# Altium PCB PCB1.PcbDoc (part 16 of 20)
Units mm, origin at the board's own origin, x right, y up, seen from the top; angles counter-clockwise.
Board outline 294.51 x 138.18 mm, 12 copper layers (Top Layer 1 _Signal, L2_GND, L3_Signals, L4_GND, L5_POWER, L6_Signals, L7_GND, L8_Signals, L9_GND, L10_POWER, L11_GND, Bottom Layer_Signals), stack 1.788 mm thick; 1254 components, 836 nets, 5699 pads, 2073 vias.
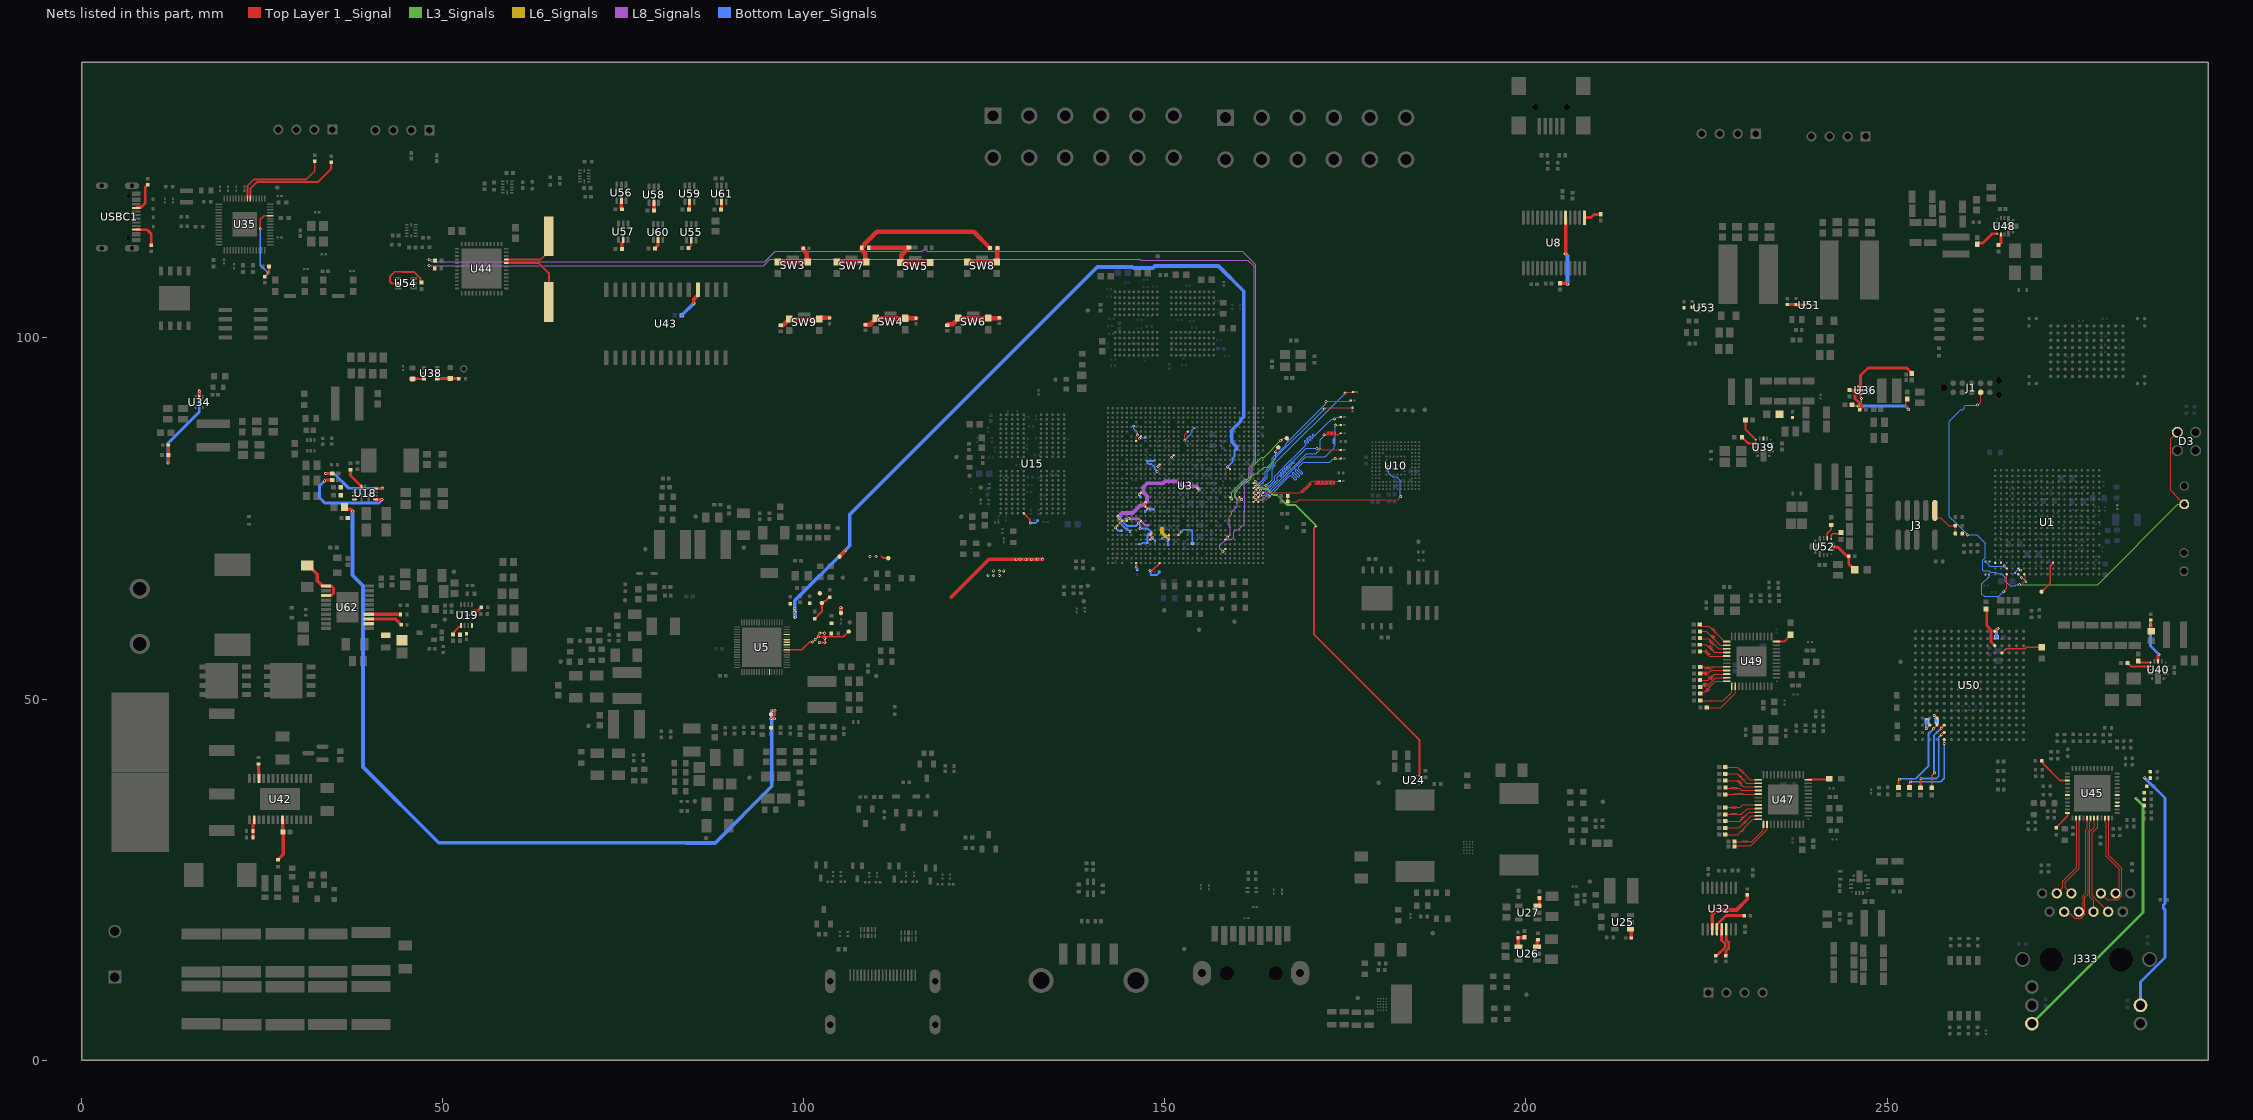
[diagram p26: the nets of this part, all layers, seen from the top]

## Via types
v1: diameter 0.4, hole 0.2, Top Layer 1 _Signal to Bottom Layer_Signals, 2009 vias
v2: diameter 0.508, hole 0.254, Top Layer 1 _Signal to Bottom Layer_Signals, 36 vias
v3: diameter 0.5, hole 0.2, Top Layer 1 _Signal to Bottom Layer_Signals, 12 vias
v4: diameter 1.27, hole 0.711, Top Layer 1 _Signal to Bottom Layer_Signals, 6 vias
v5: diameter 0.3, hole 0.2, Top Layer 1 _Signal to Bottom Layer_Signals, 5 vias
v6: diameter 0.254, hole 0.2, Top Layer 1 _Signal to Bottom Layer_Signals, 3 vias
v7: diameter 0.305, hole 0.2, Top Layer 1 _Signal to Bottom Layer_Signals, 1 vias
v8: diameter 0.254, hole 0.152, Top Layer 1 _Signal to Bottom Layer_Signals, 1 vias

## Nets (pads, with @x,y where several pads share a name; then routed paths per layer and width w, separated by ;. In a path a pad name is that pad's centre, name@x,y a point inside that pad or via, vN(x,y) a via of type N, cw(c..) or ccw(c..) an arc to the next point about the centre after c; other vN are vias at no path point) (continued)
NetR56_2: R56.2 U3.Y33 | length 19.5
  Top Layer 1 _Signal w0.132: U3.Y33@162.929,77.928 162.942,77.928 163.228,78.215 v1(163.241,78.215) ; v1(172.025,86.598) 172.416,86.598 172.482,86.598 172.482,86.996 172.639,86.996 172.639,86.572 172.797,86.572 172.797,86.996 172.954,86.996 172.954,86.572 173.111,86.572 173.111,86.996 173.268,86.996 173.268,86.572 173.425,86.572 173.425,86.996 173.583,86.996 173.583,86.572 173.74,86.572 173.74,86.662 173.897,86.662 173.897,86.598 173.993,86.598 174.06,86.598 174.258,86.796 R56.2@174.374,86.796
  Bottom Layer_Signals w0.132: v1(163.241,78.215) 163.807,78.215 164.187,78.595 164.187,78.62 164.265,78.698 164.284,78.698 167.576,81.989 167.625,81.989 169.596,83.96 170.892,83.96 171.49,84.558 171.49,85.906 171.974,86.39 171.974,86.546 v1(172.025,86.598)
NetR57_2: R57.2 U3.W33 | length 19.4
  Top Layer 1 _Signal w0.132: U3.W33@162.929,78.578 162.929,78.58 163.263,78.914 v1(163.263,78.917) ; v1(173.465,88.796) 173.522,88.796 173.775,89.049 R57.2@174.368,89.049
  Bottom Layer_Signals w0.132: v1(163.263,78.917) 163.582,79.235 164.176,79.235 165.219,80.278 165.219,80.821 165.74,81.342 165.74,81.391 167.378,83.029 167.427,83.029 169.471,85.073 169.471,85.131 169.517,85.177 ccw(c169.424,85.271) 169.517,85.364 169.321,85.56 cw(c169.404,85.643) 169.321,85.725 cw(c169.404,85.643) 169.486,85.725 169.711,85.5 ccw(c169.794,85.583) 169.876,85.5 ccw(c169.794,85.583) 169.876,85.665 169.651,85.89 cw(c169.734,85.973) 169.651,86.055 cw(c169.734,85.973) 169.816,86.055 170.041,85.83 ccw(c170.124,85.913) 170.206,85.83 ccw(c170.124,85.913) 170.206,85.995 169.981,86.22 cw(c170.064,86.303) 169.981,86.385 cw(c170.064,86.303) 170.146,86.385 170.371,86.161 ccw(c170.454,86.243) 170.536,86.161 ccw(c170.454,86.243) 170.536,86.326 170.418,86.444 cw(c170.501,86.526) 170.418,86.609 cw(c170.501,86.526) 170.583,86.609 170.673,86.519 ccw(c170.766,86.613) 170.859,86.519 172.234,87.894 173.085,88.745 173.414,88.745 v1(173.465,88.796)
NetR58_2: R58.2 U3.V32 | length 19.8
  Top Layer 1 _Signal w0.132: U3.V32@162.279,79.228 162.312,79.228 162.488,79.404 v1(162.521,79.404) ; v1(172.296,91.199) 172.343,91.247 175.573,91.247 175.675,91.348 R58.2@175.721,91.348
  Bottom Layer_Signals w0.132: v1(162.521,79.404) 162.521,79.476 162.615,79.571 162.615,79.608 162.692,79.685 162.921,79.685 163.356,80.12 163.356,80.162 163.895,80.701 163.895,81.57 164.864,82.539 164.864,83.362 165.366,83.864 165.472,83.864 166.818,85.211 166.818,85.401 172.296,90.879 v1(172.296,91.199)
NetR59_2: R59.2 U3.AA33 | length 19.4
  Top Layer 1 _Signal w0.132: U3.AA33@162.929,77.278 163.27,77.618 164.011,77.618 v1(164.422,78.029) ; v1(173.588,83.285) 173.604,83.3 174.327,83.3 R59.2@174.342,83.315
  Bottom Layer_Signals w0.132: v1(164.422,78.029) 167.048,80.656 167.296,80.904 cw(c167.396,80.803) 167.497,80.904 168.016,80.385 ccw(c168.116,80.485) 168.217,80.385 ccw(c168.116,80.485) 168.217,80.586 167.68,81.123 cw(c167.78,81.223) 167.68,81.324 cw(c167.78,81.223) 167.881,81.324 168.418,80.787 ccw(c168.518,80.887) 168.619,80.787 ccw(c168.518,80.887) 168.619,80.988 168.082,81.524 cw(c168.182,81.625) 168.082,81.725 cw(c168.182,81.625) 168.283,81.725 168.819,81.189 ccw(c168.92,81.289) 169.02,81.189 ccw(c168.92,81.289) 169.02,81.39 168.502,81.908 cw(c168.602,82.009) 168.502,82.109 169.193,82.801 172.841,82.801 173.307,83.267 173.571,83.267 v1(173.588,83.285)
NetR60_2: R60.2 U3.W34 | length 23.1
  Top Layer 1 _Signal w0.132: U3.W34@163.579,78.578 164.171,78.578 164.187,78.595 164.656,78.595 164.672,78.578 168.695,78.578 168.718,78.578 168.753,78.613 168.735,78.631 168.846,78.742 169.051,78.537 169.162,78.648 168.957,78.853 169.069,78.964 169.273,78.76 169.384,78.871 169.18,79.075 169.291,79.186 169.495,78.982 169.607,79.093 169.402,79.298 169.513,79.409 169.718,79.204 169.829,79.316 169.625,79.52 169.736,79.631 169.94,79.427 170.051,79.538 169.847,79.742 169.958,79.854 170.163,79.649 170.274,79.76 170.069,79.965 170.18,80.076 170.198,80.058 170.249,80.108 170.317,80.176 170.624,80.176 170.69,80.176 170.69,80.202 170.847,80.202 170.847,79.743 171.005,79.743 171.005,80.202 171.162,80.202 171.162,79.743 171.319,79.743 171.319,80.202 171.476,80.202 171.476,79.743 171.634,79.743 171.634,80.202 171.791,80.202 171.791,79.743 171.948,79.743 171.948,80.202 172.105,80.202 172.105,79.743 172.263,79.743 172.263,80.202 172.42,80.202 172.42,79.743 172.577,79.743 172.577,80.202 172.734,80.202 172.734,79.743 172.891,79.743 172.891,80.202 173.049,80.202 173.049,79.743 173.206,79.743 173.206,80.202 173.363,80.202 173.363,79.743 173.52,79.743 173.52,80.176 173.665,80.176 R60.2@174.223,80.176
NetR61_2: R61.2 U3.W32 | length 19.6
  Top Layer 1 _Signal w0.132: U3.W32@162.279,78.578 162.279,78.589 162.604,78.914 v1(162.604,78.926) ; v1(172.057,90.145) 172.13,90.145 172.31,90.326 175.97,90.326 R61.2@175.985,90.341
  Bottom Layer_Signals w0.132: v1(162.604,78.926) 162.604,78.993 162.87,79.259 162.87,79.33 164.149,80.609 164.149,80.886 164.16,80.896 164.16,81.46 164.567,81.867 164.567,81.937 165.079,82.45 165.079,83.167 v1(172.057,90.145)
NetR62_2: R62.2 U3.Y32 | length 19.5
  Top Layer 1 _Signal w0.132: U3.Y32@162.279,77.928 162.279,77.933 162.575,78.228 v1(162.575,78.233) ; v1(171.048,84.689) 171.676,84.689 171.875,84.489 R62.2@174.34,84.489
  Bottom Layer_Signals w0.132: v1(162.575,78.233) 162.906,78.564 163.749,78.564 164.205,79.02 164.266,79.02 165.561,80.315 165.561,80.72 165.572,80.731 165.765,80.924 cw(c165.859,80.831) 165.952,80.924 166.006,80.871 ccw(c166.079,80.944) 166.153,80.871 ccw(c166.079,80.944) 166.153,81.018 165.986,81.185 cw(c166.06,81.258) 165.986,81.332 cw(c166.06,81.258) 166.133,81.332 166.3,81.165 ccw(c166.373,81.239) 166.447,81.165 ccw(c166.373,81.239) 166.447,81.312 166.28,81.479 cw(c166.354,81.552) 166.28,81.626 cw(c166.354,81.552) 166.427,81.626 166.594,81.459 ccw(c166.667,81.533) 166.741,81.459 ccw(c166.667,81.533) 166.741,81.606 166.574,81.773 cw(c166.648,81.847) 166.574,81.92 cw(c166.648,81.847) 166.721,81.92 166.888,81.753 ccw(c166.962,81.827) 167.035,81.753 ccw(c166.962,81.827) 167.035,81.901 166.869,82.067 cw(c166.942,82.141) 166.869,82.214 cw(c166.942,82.141) 167.016,82.214 167.182,82.048 ccw(c167.256,82.121) 167.329,82.048 ccw(c167.256,82.121) 167.329,82.195 167.163,82.361 cw(c167.236,82.435) 167.163,82.508 cw(c167.236,82.435) 167.31,82.508 167.402,82.417 ccw(c167.475,82.49) 167.549,82.417 ccw(c167.475,82.49) 167.549,82.564 167.477,82.636 cw(c167.55,82.709) 167.477,82.783 cw(c167.55,82.709) 167.624,82.783 167.717,82.69 ccw(c167.791,82.763) 167.864,82.69 ccw(c167.791,82.763) 167.864,82.837 cw(c167.957,82.93) 167.864,83.023 169.57,84.729 169.67,84.729 171.007,84.729 v1(171.048,84.689)
NetR63_2: R63.2 U3.AA32 | length 19.6
  Top Layer 1 _Signal w0.132: U3.AA32@162.279,77.278 162.279,77.289 162.582,77.592 v1(162.582,77.603) ; v1(173.607,87.935) 173.614,87.929 174.356,87.929 R63.2@174.362,87.923
  Bottom Layer_Signals w0.132: v1(162.582,77.603) 163.571,77.603 164.072,78.104 164.072,78.174 164.277,78.379 164.38,78.379 169.522,83.521 172.183,83.521 173.44,84.778 173.44,85.099 173.58,85.238 173.58,85.297 ccw(c173.448,85.297) 173.448,85.428 173.329,85.428 cw(c173.329,85.507) 173.329,85.586 173.51,85.586 ccw(c173.51,85.664) 173.51,85.743 173.333,85.743 cw(c173.333,85.822) 173.333,85.9 173.51,85.9 ccw(c173.51,85.979) 173.51,86.057 173.448,86.057 cw(c173.448,86.136) 173.448,86.215 ccw(c173.448,86.346) 173.58,86.346 173.58,86.605 173.58,87.907 v1(173.607,87.935)
NetR64_2: R64.2 U3.V33 | length 19.7
  Top Layer 1 _Signal w0.132: U3.V33@162.929,79.228 163.183,79.482 163.395,79.482 163.482,79.568 164.014,79.568 v1(164.031,79.585) ; v1(174.97,92.369) 175.042,92.369 175.173,92.5 R64.2@176.07,92.5
  Bottom Layer_Signals w0.132: v1(164.031,79.585) 164.053,79.585 164.849,80.381 164.849,81.914 165.295,82.36 165.295,82.695 v1(174.97,92.369)
NetR68_1: R68.1 R69.2 U10.H5 | length 22.2
  Top Layer 1 _Signal w0.132: R68.1@167.03,78.119 167.026,78.115 167.026,77.345 R69.2@167.021,77.34 168.283,77.34 168.541,77.598 182.217,77.598 v1(182.657,78.038) ; U10.H5@180.704,82.07 180.726,82.093 180.81,82.093 180.875,82.157 v1(180.948,82.157)
  Bottom Layer_Signals w0.132: v1(180.948,82.157) 180.948,81.552 181.015,81.485 181.015,81.269 181.53,80.754 182.102,80.754 182.613,80.244 182.613,78.082 v1(182.657,78.038)
NetR70_2: R70.2 U3.W8 | length 0.8
  Top Layer 1 _Signal w0.254: v1(146.449,78.334) 146.449,78.34 146.679,78.571 U3.W8@146.679,78.578
  Bottom Layer_Signals w0.254: v1(146.449,78.334) 146.449,78.294 146.533,78.21 146.533,77.954 146.537,77.949 R70.2@146.583,77.949
NetR71_2: R71.2 U15.A8 | length 3
  Top Layer 1 _Signal w0.254: U15.A8@130.45,75.721 131.327,74.844 131.327,74.402 v1(131.354,74.374)
  Bottom Layer_Signals w0.254: v1(131.354,74.374) 132.127,74.374 132.268,74.516 132.268,74.525 132.339,74.595 132.339,74.73 132.343,74.734 R71.2@132.389,74.734
NetR76_1: R76.1 R77.2 U18.11
NetR78_1: R78.1 U18.8 | length 3.1
  Top Layer 1 _Signal w0.381: R78.1@37.244,81.767 37.244,80.943 38.755,79.431 U18.8@38.755,79.337
NetR79_2: R79.2 U18.3 | length 13.8
  Top Layer 1 _Signal w0.381: v1(33.637,80.213) 33.746,80.322 R79.2@34.705,80.322 ; U18.3@40.706,77.637 41.571,77.637 41.58,77.629 v1(41.585,77.629)
  Bottom Layer_Signals w0.381: v1(33.637,80.213) 32.942,79.518 32.942,77.879 33.665,77.156 41.168,77.156 41.585,77.573 v1(41.585,77.629)
NetR80_2: R80.2 U18.6 | length 10.7
  Top Layer 1 _Signal w0.381: v1(33.779,81.228) 33.794,81.242 R80.2@34.7,81.242 ; U18.6@40.706,79.137 40.731,79.163 41.627,79.163 41.675,79.21 v1(41.68,79.21)
  Bottom Layer_Signals w0.381: v1(33.779,81.228) 34.95,81.228 36.998,79.179 41.649,79.179 v1(41.68,79.21)
NetR82_1: R82.1 U19.8 | length 1.4
  Top Layer 1 _Signal w0.381: U19.8@54.238,62.133 54.303,62.199 54.853,62.199 55.337,62.683 R82.1@55.337,62.708
NetR83_2: R83.2 U19.3 | length 1.9
  Top Layer 1 _Signal w0.254: R83.2@51.435,58.926 51.583,59.074 51.583,59.303 52.24,59.96 52.536,59.96 52.538,59.962 U19.3@52.538,60.183
NetR85_2: R85.2 R87.2 U19.6
NetR91_2: R91.2 U3.AP12 | length 3.7
  Top Layer 1 _Signal w0.254: v1(147.965,67.814) 148.265,67.814 U3.AP12@149.279,68.828
  Bottom Layer_Signals w0.254: v1(147.965,67.814) 147.993,67.786 147.993,67.322 148.146,67.169 148.859,67.169 149.245,67.555 R91.2@149.245,67.58
NetR98_2: R98.2 U3.AH16 | length 4
  Top Layer 1 _Signal w0.203: U3.AH16@151.879,72.728 151.879,72.745 152.247,73.113 v1(152.247,73.13)
  Bottom Layer_Signals w0.203: v1(152.247,73.13) 152.567,73.449 153.538,73.449 153.809,73.179 153.809,71.582 R98.2@153.845,71.545
NetR104_1: R104.1 U3.AF3 | length 1.4
  Top Layer 1 _Signal w0.203: v1(143.138,73.713) 143.146,73.713 143.429,73.996 U3.AF3@143.429,74.028
  Bottom Layer_Signals w0.203: v1(143.138,73.713) 143.529,73.323 R104.1@143.951,73.323
NetR127_1: R127.1 U25.1 | length 1.3
  Top Layer 1 _Signal w0.508: U25.1@214.496,18.137 214.523,18.137 214.569,18.091 R127.1@214.569,16.917
NetR131_2: R131.2 U26.3 | length 1
  Top Layer 1 _Signal w0.457: U26.3@201.553,15.69 201.553,16.581 201.646,16.674 R131.2@201.671,16.674
NetR132_2: R132.2 U27.3 | length 1.3
  Top Layer 1 _Signal w0.457: U27.3@201.607,21.375 201.804,21.375 201.875,21.446 R132.2@201.875,22.443
NetR133_1: R133.1 R134.1 U26.4 | length 2.2
  Top Layer 1 _Signal w0.457: U26.4@198.953,15.69 198.953,16.855 198.883,16.925 R133.1@198.883,16.943 199.736,16.943 199.794,17.001 R134.1@199.794,17.026
NetR139_2: R139.2 U36.4 | length 9.2
  Top Layer 1 _Signal w0.381: 246.252,93.455 246.311,93.513 246.311,94.77 247.363,95.823 252.728,95.823 253.43,95.121 R139.2@253.43,95.096
NetR140_1: R140.1 R142.2 U36.5 | length 4.8
  Top Layer 1 _Signal w0.381: R142.2@244.824,92.806 244.918,92.712 245.282,92.712 ; R140.1@246.23,90.062 246.274,90.106 246.274,90.108 246.458,90.292 246.458,90.778 246.176,91.06 246.106,91.06 245.58,91.587 245.58,92.415 245.282,92.712 ; U36.5@246.289,92.753 245.323,92.753 245.282,92.712
NetR141_1: R141.1 R143.2 U36.6 | length 11.8
  Top Layer 1 _Signal w0.254: R143.2@245.15,90.739 245.28,90.61 245.956,90.61 v1(245.984,90.582) ; U36.6@246.289,92.253 246.289,91.802 246.464,91.627 v1(246.464,91.614) ; R141.1@252.788,91.56 252.591,91.363 252.591,90.522 v1(253.002,90.111)
  Bottom Layer_Signals w0.254: v1(245.984,90.582) 246.437,91.035 246.437,91.586 v1(246.464,91.614)
  Bottom Layer_Signals w0.4: v1(245.984,90.582) 252.531,90.582 v1(253.002,90.111)
NetR146_1: R146.1 R147.2 U34.5 | length 15.2
  Top Layer 1 _Signal w0.4: v1(11.986,82.68) 12.022,82.716 R146.1@12.022,85.17 ; U34.5@16.269,91.825 16.269,92.623 v1(16.288,92.643)
  Bottom Layer_Signals w0.4: v1@12.063,82.757 v1(11.986,82.68) 11.986,85.433 16.288,89.735 v1(16.288,92.643)
NetR157_2: R157.2 R158.1 U40.3 | length 7.2
  Top Layer 1 _Signal w0.381: R157.2@286.489,60.946 v1(286.489,60.324) 286.489,60.319 286.586,60.222 R158.1@286.586,59.392 ; U40.3@287.528,55.237 287.528,56.051 v1(287.648,56.171)
  Bottom Layer_Signals w0.381: v1(286.489,60.324) 286.489,57.331 v1(287.648,56.171)
NetR159_2: R159.2 U40.6 | length 3.2
  Top Layer 1 _Signal w0.254: R159.2@283.323,54.955 283.753,54.524 U40.6@286.366,54.524
NetR160_2: R160.2 U40.5 | length 1.8
  Top Layer 1 _Signal w0.3: R160.2@284.775,55.257 284.775,55.232 284.95,55.057 U40.5@286.474,55.057
NetR161_2: R161.2 U48.5 | length 3.3
  Top Layer 1 _Signal w0.381: R161.2@262.505,112.976 262.505,113.001 262.64,113.135 263.276,113.135 264.551,114.41 U48.5@265.236,114.41
NetR163_2: R163.2 U48.6 | length 1.6
  Top Layer 1 _Signal w0.381: R163.2@265.444,112.868 265.769,113.193 U48.6@265.769,114.302
NetR164_2: R164.2 U8.1 | length 2.4
  Top Layer 1 _Signal w0.381: U8.1@208.091,116.664 209.019,116.664 209.463,117.108 R164.2@210.356,117.108
NetR165_2: R165.2 U8.5 | length 10.4
  Top Layer 1 _Signal w0.508: R165.2@204.745,107.566 205.618,107.566 v1(205.746,107.438) ; v1(205.488,111.655) 205.491,111.658 U8.5@205.491,116.664
  Bottom Layer_Signals w0.508: v1(205.488,111.655) 205.746,111.396 v1(205.746,107.438)
NetR168_1: R168.1 U32.14 | length 3.3
  Top Layer 1 _Signal w0.381: R168.1@227.666,14.475 227.668,14.475 227.712,14.519 227.712,15.091 228.07,15.45 228.07,16.291 227.743,16.618 U32.14@227.743,17.435
NetR169_1: R169.1 U32.13 | length 4.5
  Top Layer 1 _Signal w0.381: R169.1@226.302,14.475 226.346,14.519 226.483,14.519 227.606,15.642 227.606,16.098 227.093,16.611 U32.13@227.093,18.11
NetR170_1: R170.1 U32.12 | length 5
  Top Layer 1 _Signal w0.381: U32.12@226.443,18.11 226.443,18.766 226.647,18.97 226.647,18.989 227.698,20.04 229.985,20.04 229.993,20.032 230.196,20.032 R170.1@230.239,19.986 R170.1@230.239,19.986
NetR171_1: R171.1 U32.11 | length 8.4
  Top Layer 1 _Signal w0.508: U32.11@225.793,18.11 225.793,20.133 226.435,20.775 229.145,20.775 230.65,22.279 R171.1@230.65,22.885
NetR176_1: R176.1 U3.AP7 | length 1
  Top Layer 1 _Signal w0.203: U3.AP7@146.029,68.828 146.029,68.32 v1(146.033,68.317)
  Bottom Layer_Signals w0.203: v1(146.033,68.317) 146.071,68.279 146.071,67.992 146.078,67.985 146.078,67.96 146.152,67.886 R176.1@146.177,67.886
NetR177_2: R177.2 SW3.1 SW3.2 | length 6.3
  Top Layer 1 _Signal w0.635: SW3.1@96.427,110.519 96.479,110.468 SW3.2@100.476,110.468 ; R177.2@99.913,112.425 99.913,112.195 100.395,111.713 100.395,110.549 SW3.2@100.476,110.468 ; SW3.2@100.527,110.519 SW3.2@100.476,110.468
NetR178_1: R178.1 R180.2 SW5.1 SW5.2 | length 12.2
  Top Layer 1 _Signal w0.635: R180.2@109.059,112.497 111.788,112.497 111.793,112.503 R178.1@114.557,112.503 114.557,112.484 113.513,111.44 113.513,110.58 SW5.1@113.381,110.447 113.432,110.396 117.429,110.396 SW5.2@117.481,110.447
NetR179_2: R179.2 SW4.1 SW4.2 U17.1 | length 7.4
  Top Layer 1 _Signal w0.635: U17.1@108.537,101.852 109.131,101.852 109.966,102.687 SW4.1@109.966,102.737 ; SW4.1@109.98,102.649 110.018,102.686 114.015,102.686 SW4.2@114.066,102.737 115.525,102.737 R179.2@115.538,102.75
NetR180_1: R180.1 R182.2 SW7.1 SW7.2 | length 26.1
  Top Layer 1 _Signal w0.635: SW7.1@104.571,110.514 104.622,110.463 108.62,110.463 SW7.2@108.671,110.514 108.539,110.647 108.539,111.675 108.019,112.195 R180.1@108.017,112.497 R180.1@108.017,112.497 108.366,112.846 108.366,112.964 110.102,114.7 123.542,114.7 R182.2@125.785,112.457
NetR181_2: R181.2 SW6.1 SW6.2 U29.1 | length 7.8
  Top Layer 1 _Signal w0.635: U29.1@119.884,101.778 119.992,101.886 120.61,101.886 121.419,102.695 SW6.1@121.419,102.745 121.47,102.694 125.467,102.694 SW6.2@125.519,102.745 127.043,102.745 R181.2@127.229,102.745
NetR182_1: R182.1 SW8.1 SW8.2 | length 6.2
  Top Layer 1 _Signal w0.635: SW8.1@122.643,110.516 122.694,110.465 126.691,110.465 SW8.2@126.743,110.516 126.804,110.577 126.804,112.488 R182.1@126.835,112.457
NetR183_2: R183.2 SW9.1 SW9.2 U33.1 | length 7.3
  Top Layer 1 _Signal w0.635: U33.1@96.789,101.746 97.185,101.746 98.006,102.567 98.006,102.642 98.041,102.607 99.023,102.607 99.052,102.578 101.084,102.578 101.113,102.607 102.096,102.607 SW9.2@102.118,102.629 ; SW9.2@102.118,102.634 102.251,102.766 R183.2@103.568,102.766
NetR184_2: R184.2 R186.2 U39.3
NetR185_2: R185.2 U39.5 | length 3.3
  Top Layer 1 _Signal w0.254: R185.2@230.414,88.643 230.414,87.313 U39.5@231.822,85.904
NetR187_2: R187.2 U47.26 | length 6
  Top Layer 1 _Signal w0.132: R187.2@227.619,39.622 229.249,39.622 229.558,39.314 229.604,39.267 229.69,39.353 229.801,39.242 229.697,39.138 229.809,39.027 229.912,39.131 230.024,39.019 229.92,38.916 230.031,38.804 230.135,38.908 230.246,38.797 230.142,38.693 230.253,38.582 230.271,38.6 230.401,38.47 230.537,38.335 U47.26@232.187,38.335
NetR189_2: R189.2 U49.29 | length 5.7
  Top Layer 1 _Signal w0.132: R189.2@224.096,56.596 224.634,56.596 224.727,56.596 224.932,56.8 225.044,56.689 224.834,56.48 224.946,56.369 225.155,56.578 225.266,56.467 225.057,56.258 225.168,56.147 225.377,56.356 225.488,56.245 225.297,56.053 225.396,55.955 225.508,55.955 U49.29@227.79,55.955
NetR190_1: R190.1 USBC1.B5 | length 3.9
  Top Layer 1 _Signal w0.381: USBC1.B5@7.558,115.005 7.849,115.005 7.864,114.99 9.078,114.99 9.364,114.704 9.364,114.67 9.65,114.384 9.65,112.814 R190.1@9.65,112.807
NetR192_2: R192.2 USBC1.A5 | length 4.2
  Top Layer 1 _Signal w0.381: USBC1.A5@7.558,118.005 7.598,118.046 8.206,118.046 8.83,118.669 8.83,120.926 9.086,121.182 9.094,121.182 9.14,121.228 R192.2@9.14,121.235
NetR196_1: R196.1 R197.2 U35.26 | length 11.1
  Top Layer 1 _Signal w0.254: v1(24.745,115.068) 24.745,116.406 25.267,116.928 U35.26@26.144,116.928 ; R197.2@25.356,108.466 25.359,108.466 v1@25.85,108.957 ; v1(25.815,108.991) 25.815,109.031 25.959,109.174 R196.1@25.959,109.873
  Bottom Layer_Signals w0.254: v1(24.745,115.068) 24.745,110.062 v1(25.815,108.991)
NetR201_1: R201.1 U35.36 | length 14.6
  Top Layer 1 _Signal w0.254: U35.36@23.369,119.303 23.369,120.663 24.276,121.57 32.673,121.57 34.544,123.44 R201.1@34.544,124.349
NetR202_1: R202.1 U35.37 | length 13.3
  Top Layer 1 _Signal w0.254: U35.37@22.969,119.303 22.969,121.075 23.834,121.94 31.103,121.94 32.282,123.118 R202.1@32.282,124.479
NetR205_2: R205.2 R207.2 U42.2 | length 2.6
  Top Layer 1 _Signal w0.457: R205.2@23.726,30.805 23.726,30.847 23.743,30.865 R207.2@23.743,31.72 23.743,32.572 23.876,32.705 23.876,33.268 U42.2@23.904,33.296
NetR212_1: R212.1 U42.26 | length 2
  Top Layer 1 _Signal w0.457: R212.1@24.499,40.987 24.499,40.069 24.526,40.041 24.526,39.025 U42.26@24.554,38.996
NetR214_1: R214.1 U43.18 | length 4.4
  Top Layer 1 _Signal w0.508: v1(84.788,104.794) 84.788,105.387 85.348,105.947 U43.18@85.348,106.647
  Bottom Layer_Signals w0.508: R214.1@83.117,103.123 v1(84.788,104.794)
NetR215_1: R215.1 U47.12 | length 2.9
  Top Layer 1 _Signal w0.254: U47.12@239.088,38.835 241.837,38.835 R215.1@241.972,38.969
NetR216_2: R216.2 U47.29 | length 5.9
  Top Layer 1 _Signal w0.132: R216.2@227.616,36.767 227.685,36.835 228.929,36.835 228.995,36.835 228.995,36.983 229.152,36.983 229.152,36.809 229.309,36.809 229.309,36.983 229.466,36.983 229.466,36.809 229.623,36.809 229.623,36.983 229.781,36.983 229.781,36.809 229.938,36.809 229.938,36.983 230.095,36.983 230.095,36.835 230.182,36.835 U47.29@232.187,36.835
NetR217_2: R217.2 U47.37 | length 6
  Top Layer 1 _Signal w0.132: R217.2@228.889,30.246 230.036,30.246 230.102,30.246 230.102,30.354 230.259,30.354 230.259,30.22 230.417,30.22 230.417,30.354 230.574,30.354 230.574,30.22 230.731,30.22 230.731,30.27 230.888,30.27 230.888,30.246 230.983,30.246 231.273,30.246 232.887,31.86 U47.37@232.887,32.634
NetR218_2: R218.2 U47.28 | length 6
  Top Layer 1 _Signal w0.132: R218.2@227.623,37.732 227.741,37.614 228.333,37.614 228.399,37.614 228.399,37.749 228.556,37.749 228.556,37.54 228.714,37.54 228.714,37.749 228.871,37.749 228.871,37.54 229.028,37.54 229.028,37.749 229.185,37.749 229.185,37.54 229.343,37.54 229.343,37.64 229.5,37.64 229.5,37.614 229.561,37.614 229.647,37.528 229.84,37.335 U47.28@232.187,37.335
NetR219_2: R219.2 U47.27 | length 6
  Top Layer 1 _Signal w0.132: R219.2@227.62,38.692 229.248,38.692 229.343,38.598 229.39,38.551 229.557,38.718 229.668,38.607 229.483,38.422 229.594,38.311 229.779,38.496 229.89,38.384 229.705,38.2 229.816,38.088 229.846,38.118 229.957,38.007 229.946,37.995 230.094,37.847 230.106,37.835 U47.27@232.187,37.835
NetR220_2: R220.2 U49.37 | length 5.7
  Top Layer 1 _Signal w0.132: R220.2@224.124,49.789 225.638,49.789 225.704,49.789 225.704,49.809 225.861,49.809 225.861,49.789 226.67,49.789 227.343,49.789 228.491,50.937 U49.37@228.491,51.754
NetR221_2: R221.2 U47.25 | length 6
  Top Layer 1 _Signal w0.132: R221.2@227.618,40.57 229.284,40.57 229.514,40.341 229.561,40.294 229.635,40.369 229.747,40.258 229.654,40.165 229.765,40.054 229.858,40.147 229.969,40.036 229.876,39.943 229.987,39.831 230.071,39.915 230.182,39.804 230.116,39.738 230.235,39.62 231.02,38.835 U47.25@232.187,38.835
NetR222_2: R222.2 U47.32 | length 6
  Top Layer 1 _Signal w0.132: R222.2@227.606,34.985 228.346,34.985 228.412,34.985 228.412,35.115 228.569,35.115 228.569,34.898 228.726,34.898 228.726,35.115 228.883,35.115 228.883,34.898 229.041,34.898 229.041,35.115 229.198,35.115 229.198,34.914 229.355,34.914 229.355,34.985 229.615,34.985 229.687,34.985 230.037,35.335 U47.32@232.187,35.335
NetR223_2: R223.2 U47.38 | length 6.2
  Top Layer 1 _Signal w0.132: R223.2@228.888,29.562 229.036,29.71 231.113,29.71 233.387,31.984 U47.38@233.387,32.634
NetR224_2: R224.2 U47.33 | length 6
  Top Layer 1 _Signal w0.132: R224.2@227.602,34.035 228.365,34.035 228.431,34.035 228.431,34.192 228.588,34.192 228.588,34.01 228.745,34.01 228.745,34.192 228.903,34.192 228.903,34.01 229.06,34.01 229.06,34.192 229.217,34.192 229.217,34.016 229.374,34.016 229.374,34.035 229.67,34.035 229.821,34.035 230.621,34.835 U47.33@232.187,34.835
NetR225_2: R225.2 U47.34 | length 6
  Top Layer 1 _Signal w0.132: R225.2@227.605,33.097 229.665,33.097 229.753,33.185 229.8,33.232 229.694,33.337 229.805,33.449 229.929,33.325 230.04,33.436 229.916,33.56 230.028,33.671 230.151,33.547 230.263,33.658 230.172,33.749 230.283,33.86 230.356,33.787 230.518,33.949 230.903,34.335 U47.34@232.187,34.335
NetR226_2: R226.2 U47.35 | length 6
  Top Layer 1 _Signal w0.132: R226.2@227.601,32.157 229.497,32.157 230.068,32.728 230.114,32.775 230.055,32.835 230.166,32.946 230.331,32.78 230.443,32.891 230.277,33.057 230.388,33.168 230.477,33.08 230.588,33.191 230.559,33.22 230.679,33.339 231.174,33.835 U47.35@232.187,33.835
NetR227_2: R227.2 U47.36 | length 6
  Top Layer 1 _Signal w0.132: R227.2@227.601,31.238 229.337,31.238 229.662,31.563 229.709,31.609 229.691,31.627 229.802,31.739 229.932,31.608 230.044,31.719 229.913,31.85 230.024,31.961 230.087,31.899 230.198,32.01 230.153,32.054 230.31,32.211 231.434,33.335 U47.36@232.187,33.335
NetR230_2: R230.2 U39.6 | length 2.2
  Top Layer 1 _Signal w0.3: R230.2@229.906,86.236 230.564,85.577 230.599,85.577 230.805,85.371 U39.6@231.714,85.371
NetR231_2: R231.2 R233.2 U52.3 | length 4.9
  Top Layer 1 _Signal w0.381: U52.3@242.511,71.039 243.172,71.039 244.417,69.794 244.661,69.794 244.704,69.751 244.704,68.716 245.5,67.921 R231.2@245.523,67.921
NetR232_2: R232.2 U52.5 | length 2
  Top Layer 1 _Signal w0.254: U52.5@242.266,72.159 242.266,72.694 242.451,72.879 243.468,72.879 R232.2@243.626,73.037
NetR234_2: R234.2 U52.6 | length 2.1
  Top Layer 1 _Signal w0.254: U52.6@241.733,72.267 241.733,72.93 242.273,73.471 R234.2@242.273,74.107
NetR235_1: R235.1 U49.12 | length 2.3
  Top Layer 1 _Signal w0.254: U49.12@234.691,57.955 235.764,57.955 236.626,58.817 R235.1@236.626,58.867
NetR236_2: R236.2 U49.28 | length 5.7
  Top Layer 1 _Signal w0.132: R236.2@224.088,57.514 224.979,57.514 225.237,57.257 225.283,57.21 225.493,57.42 225.605,57.309 225.377,57.081 225.488,56.97 225.716,57.198 225.827,57.087 225.599,56.859 225.71,56.748 225.824,56.861 225.935,56.75 225.839,56.654 225.91,56.583 226.039,56.455 U49.28@227.79,56.455
NetR237_2: R237.2 U49.27 | length 5.7
  Top Layer 1 _Signal w0.132: R237.2@224.092,58.443 224.209,58.326 225.339,58.326 225.376,58.289 225.423,58.242 225.441,58.26 225.552,58.149 225.396,57.993 225.507,57.882 225.663,58.038 225.774,57.927 225.619,57.771 225.73,57.66 225.886,57.815 225.997,57.704 225.841,57.548 225.952,57.437 226.108,57.593 226.219,57.482 226.187,57.45 226.298,57.339 226.312,57.353 226.372,57.293 226.71,56.955 U49.27@227.79,56.955
NetR238_2: R238.2 U49.26 | length 5.7
  Top Layer 1 _Signal w0.132: R238.2@224.091,59.369 224.974,59.369 225.594,58.749 225.641,58.702 225.825,58.886 225.936,58.775 225.734,58.573 225.845,58.462 226.047,58.664 226.158,58.553 225.956,58.351 226.068,58.239 226.109,58.281 226.22,58.169 226.197,58.146 226.467,57.876 226.888,57.455 U49.26@227.79,57.455
NetR239_2: R239.2 U49.25 | length 5.8
  Top Layer 1 _Signal w0.132: R239.2@224.083,60.307 224.292,60.098 225.345,60.098 225.701,59.742 225.747,59.695 225.884,59.831 225.995,59.72 225.841,59.566 225.952,59.455 226.106,59.609 226.217,59.498 226.063,59.343 226.174,59.232 226.263,59.321 226.374,59.21 226.303,59.139 226.506,58.936 227.361,58.082 227.361,58.004 227.41,57.955 U49.25@227.79,57.955
NetR240_2: R240.2 U49.32 | length 5.7
  Top Layer 1 _Signal w0.132: R240.2@224.121,54.46 224.127,54.455 224.629,54.455 224.694,54.455 224.694,54.48 224.852,54.48 224.852,54.18 225.009,54.18 225.009,54.48 225.166,54.48 225.166,54.18 225.323,54.18 225.323,54.48 225.481,54.48 225.481,54.18 225.638,54.18 225.638,54.48 225.795,54.48 225.795,54.364 225.952,54.364 225.952,54.455 226.725,54.455 U49.32@227.79,54.455
NetR241_2: R241.2 U49.38 | length 5.7
  Top Layer 1 _Signal w0.132: R241.2@225.03,48.819 226.978,48.819 228.991,50.831 U49.38@228.991,51.754
NetR242_1: R242.1 U50.N13 | length 1.5
  Top Layer 1 _Signal w0.3: v1(256.532,47.742) 256.544,47.742 256.907,47.379 U50.N13@256.919,47.379
  Bottom Layer_Signals w0.2: v1(256.532,47.742) 256.532,47.687 256.665,47.555 256.665,47.172 R242.1@256.894,46.943
NetR242_2: R242.2 U50.P14 | length 1.7
  Top Layer 1 _Signal w0.254: v1(255.435,45.932) 255.472,45.932 U50.P14@255.919,46.379
  Bottom Layer_Signals w0.381: v1(255.435,45.932) 255.438,45.936 255.438,46.841 R242.2@255.54,46.943
NetR243_2: R243.2 U49.33 | length 5.7
  Top Layer 1 _Signal w0.132: R243.2@224.12,53.558 224.521,53.558 224.587,53.558 224.587,53.807 224.744,53.807 224.744,53.386 224.901,53.386 224.901,53.807 225.059,53.807 225.059,53.386 225.216,53.386 225.216,53.795 225.373,53.795 225.373,53.765 225.505,53.765 225.606,53.866 225.695,53.955 U49.33@227.79,53.955
NetR244_2: R244.2 U49.34 | length 5.7
  Top Layer 1 _Signal w0.132: R244.2@224.111,52.616 225.251,52.616 225.355,52.719 225.401,52.766 225.26,52.907 225.372,53.018 225.707,52.683 225.818,52.794 225.483,53.129 225.594,53.24 225.85,52.984 225.961,53.095 225.846,53.211 226.053,53.417 226.09,53.455 U49.34@227.79,53.455
NetR245_2: R245.2 U49.35 | length 5.7
  Top Layer 1 _Signal w0.132: R245.2@224.114,51.676 224.323,51.885 224.534,51.885 224.6,51.885 224.6,52.149 224.758,52.149 224.758,51.687 224.915,51.687 224.915,52.149 225.072,52.149 225.072,51.854 225.229,51.854 225.229,51.888 225.345,52.003 226.296,52.955 U49.35@227.79,52.955
NetR246_2: R246.2 U49.36 | length 5.7
  Top Layer 1 _Signal w0.132: R246.2@224.114,50.737 224.323,50.946 224.695,50.946 224.78,51.031 224.827,51.077 224.768,51.136 224.88,51.247 225.119,51.007 225.23,51.118 224.991,51.358 225.102,51.469 225.334,51.237 225.445,51.349 225.271,51.522 225.591,51.842 226.204,52.455 U49.36@227.79,52.455
NetR250_1: R250.1 U50.E3 | length 5.6
  Top Layer 1 _Signal w0.381: R250.1@263.715,62.471 263.812,62.374 263.812,60.182 264.411,59.583 264.411,57.902 264.919,57.394 U50.E3@264.919,57.379
NetR252_1: R252.1 U50.E1 | length 1.9
  Top Layer 1 _Signal w0.381: U50.E1@264.919,59.379 264.934,59.379 265.331,59.776 265.345,59.776 v1(265.349,59.78)
  Bottom Layer_Signals w0.381: R252.1@265.156,58.554 265.156,59.582 265.349,59.774 v1(265.349,59.78)
NetR255_1: R255.1 R267.2 U51.5 | length 2.4
  Top Layer 1 _Signal w0.381: R255.1@236.185,104.629 237.394,104.629 R267.2@237.411,104.646 237.511,104.545 U51.5@238.511,104.545
NetR256_2: R256.2 U50.D4 | length 5.8
  Top Layer 1 _Signal w0.254: U50.D4@265.919,56.379 266.49,56.95 269.097,56.95 269.317,57.171 R256.2@271.409,57.171
NetR257_1: R257.1 U50.N14 | length 12.1
  Top Layer 1 _Signal w0.254: R257.1@251.603,37.741 251.603,38.714 251.741,38.852 v1(251.741,38.891) ; v1(256.444,45.904) U50.N14@256.919,46.379
  Bottom Layer_Signals w0.254: v1(251.741,38.891) 251.769,38.919 251.872,38.919 251.915,38.962 253.952,38.962 255.765,40.775 255.765,45.225 v1(256.444,45.904)
NetR259_1: R259.1 U50.M14 | length 9.4
  Top Layer 1 _Signal w0.254: R259.1@256.19,37.716 256.19,39.372 256.561,39.743 v1(256.561,39.783) ; v1(257.51,45.97) U50.M14@257.919,46.379
  Bottom Layer_Signals w0.254: v1(256.561,39.783) 256.561,39.822 256.487,39.897 256.487,44.947 v1(257.51,45.97)
NetR261_1: R261.1 U50.M15 | length 10.3
  Top Layer 1 _Signal w0.254: R261.1@254.632,37.721 254.632,38.863 254.723,38.954 v1(254.723,38.994) ; v1(257.501,45.029) 257.519,45.029 257.87,45.379 U50.M15@257.919,45.379
  Bottom Layer_Signals w0.254: v1(254.723,38.994) 256.846,38.994 257.15,39.298 257.15,44.679 v1(257.501,45.029)
NetR262_1: R262.1 U50.M16 | length 11.1
  Top Layer 1 _Signal w0.254: R262.1@253.128,37.749 253.128,38.413 253.226,38.512 v1(253.226,38.551) ; v1(257.919,43.84) U50.M16@257.919,44.379
  Bottom Layer_Signals w0.254: v1(253.226,38.551) 257.466,38.551 257.919,39.005 v1(257.919,43.84)
NetR269_1: R269.1 R271.2 U53.5
NetR272_1: R272.1 U54.5 | length 7.4
  Top Layer 1 _Signal w0.254: U54.5@43.815,107.559 42.923,107.559 42.723,107.758 42.723,108.552 43.339,109.168 44.314,109.168 44.333,109.149 45.995,109.149 46.941,108.203 46.941,107.816 R272.1@47.089,107.668
NetR274_2: R274.2 U3.G8 | length 1.2
  Top Layer 1 _Signal w0.152: v1(146.488,86.065) 146.535,86.112 146.535,86.188 146.679,86.333 U3.G8@146.679,86.378
  Bottom Layer_Signals w0.152: v1(146.488,86.065) 146.555,86.065 146.676,86.186 R274.2@147.269,86.186
NetR275_1: R275.1 U3.F18 | length 3.6
  Top Layer 1 _Signal w0.161: v1@152.748,85.824 v1(152.748,85.834) 152.756,85.842 152.756,86.605 U3.F18@153.179,87.028
  Bottom Layer_Signals w0.161: v1(152.748,85.834) 153.647,86.732 153.647,87.143 153.994,87.49 R275.1@154.04,87.49
NetR276_1: R276.1 U55.5 | length 1.3
  Top Layer 1 _Signal w0.254: R276.1@84.032,112.43 84.341,112.739 84.341,113.457 U55.5@84.414,113.53
NetR278_1: R278.1 U56.5 | length 1
  Top Layer 1 _Signal w0.508: U56.5@74.713,118.795 74.713,117.963 R278.1@74.857,117.818
NetR279_1: R279.1 U57.5 | length 1.3
  Top Layer 1 _Signal w0.4: R279.1@74.848,112.331 74.848,113.19 75.008,113.349 U57.5@75.008,113.599
NetR280_1: R280.1 U58.5 | length 1.1
  Top Layer 1 _Signal w0.508: U58.5@79.244,118.739 79.249,118.734 79.249,117.662 R280.1@79.255,117.657
NetR281_1: R281.1 U59.5 | length 1.1
  Top Layer 1 _Signal w0.381: R281.1@84.131,117.812 84.175,117.856 84.175,118.869 U59.5@84.185,118.879
NetR282_1: R282.1 U60.5 | length 1.3
  Top Layer 1 _Signal w0.4: R282.1@79.411,112.389 79.823,112.801 U60.5@79.823,113.566
NetR284_1: R284.1 U61.5 | length 1.1
  Top Layer 1 _Signal w0.381: R284.1@88.556,117.759 88.604,117.808 88.604,118.839 U61.5@88.614,118.849
NetR294_1: R294.1 R297.2 U62.2
NetR295_1: R295.1 U62.4 | length 4.4
  Top Layer 1 _Signal w0.457: U62.4@39.768,61.736 44.125,61.736 44.153,61.707 R295.1@44.153,61.694
NetR298_2: R298.2 U62.3 | length 4.8
  Top Layer 1 _Signal w0.457: U62.3@39.768,61.086 43.455,61.086 44.261,60.279 R298.2@44.261,60.277
NetR299_1: R299.1 U62.11 U62.13 | length 7.3
  Top Layer 1 _Signal w0.457: R299.1@31.224,68.514 31.399,68.514 32.642,67.271 32.642,66.394 33.4,65.636 U62.11@33.868,65.636 33.87,65.633 34.612,65.633 34.88,65.365 34.88,64.661 34.559,64.34 33.871,64.34 U62.13@33.868,64.336
NetR303_1: R303.1 U3.H7 | length 2.4
  Top Layer 1 _Signal w0.152: U3.H7@146.029,85.728 146.029,86.39 146.174,86.535 v1(146.221,86.535)
  Bottom Layer_Signals w0.152: R303.1@145.705,87.82 145.705,87.441 146.183,86.964 146.183,86.573 v1(146.221,86.535)
NetR305_1: R305.1 U3.AL26 | length 160.3
  Top Layer 1 _Signal w0.132: v1(48.131,110.866) 48.133,110.865 48.756,110.865 48.756,110.925 48.94,110.741 R305.1@48.94,110.717 ; v1(158.043,70.442) U3.AL26@158.379,70.778
  L8_Signals w0.165: v1(48.131,110.866) 48.47,110.528 94.571,110.528 96.031,111.988 116.385,111.988 116.588,112.192 116.891,112.192 117.095,111.988 160.735,111.988 162.594,110.129 162.594,82.66 161.942,82.009 161.942,81.248 161.859,81.164 161.859,80.502 161.663,80.307 161.306,79.95 161.212,79.95 160.997,79.735 160.997,79.079 161.032,79.044 161.032,76.167 160.99,76.125 160.99,74.906 161.016,74.881 161.016,74.184 160.801,73.969 160.702,73.969 160.159,73.426 159.831,73.426 159.674,73.268 159.674,73.264 159.564,73.155 159.564,72.418 159.267,72.12 158.938,72.12 158.865,72.047 158.399,72.047 157.634,71.281 157.634,70.851 v1(158.043,70.442)
NetR306_1: R306.1 U3.AJ26 | length 155.9
  Top Layer 1 _Signal w0.165: v1(48.118,110.029) 48.521,110.029 48.755,109.794 48.755,109.749 R306.1@48.923,109.582 ; U3.AJ26@158.379,72.078 v1(158.713,72.413)
  L8_Signals w0.165: v1(48.118,110.029) 94.424,110.029 95.27,110.875 146.531,110.875 146.634,110.771 161.503,110.771 162.345,109.93 162.345,82.773 161.693,82.121 161.693,81.351 161.61,81.267 161.61,80.605 161.414,80.41 161.203,80.199 161.109,80.199 160.749,79.838 160.749,79.744 160.015,79.011 160.015,78.764 159.694,78.442 159.694,78.139 160.007,77.826 160.007,76.989 160.034,76.962 160.034,76.711 159.275,75.952 159.275,75.573 158.941,75.239 158.941,73.842 159.072,73.711 159.072,72.772 v1(158.713,72.413)
NetR335_1: R335.1 R339.1 U38.4 | length 3
  Top Layer 1 _Signal w0.381: U38.4@49.245,94.359 49.27,94.384 51.021,94.384 R335.1@51.046,94.409 51.071,94.384 52.19,94.384 R339.1@52.215,94.359
NetR400_1: R400.1 U45.39 | length 4.8
  Top Layer 1 _Signal w0.254: R400.1@271.447,41.434 271.557,41.323 271.557,41.098 273.952,38.703 U45.39@274.974,38.703
NetR402_2: R402.2 U45.48 | length 2.7
  Top Layer 1 _Signal w0.254: R402.2@273.429,32.159 273.445,32.159 273.556,32.27 273.556,32.345 274.974,33.764 U45.48@274.974,34.203
NetTP6_1: TP6.1 U3.Y29 | length 11.6
  Top Layer 1 _Signal w0.132: U3.Y29@160.329,77.928 v1(160.64,77.615) ; v1(165.327,84.214) 165.327,84.287 165.457,84.417 165.457,84.468 165.707,84.718 TP6.1@165.707,84.845
  L3_Signals w0.113: v1(160.64,77.615) 159.997,77.615 159.72,77.892 159.72,78.755 161.125,80.16 161.456,80.16 162.478,81.182 162.746,81.182 163.662,82.099 164.167,82.099 165.327,83.259 v1(165.327,84.214)
NetTP7_1: TP7.1 U3.Y27 | length 12.6
  Top Layer 1 _Signal w0.132: U3.Y27@159.029,77.928 159.043,77.928 159.043,77.921 159.263,77.701 v1(159.27,77.701) ; v1(166.075,85.838) 166.148,85.838 166.392,86.083 166.876,86.083 TP7.1@166.89,86.097
  L3_Signals w0.113: v1(159.27,77.701) 159.27,78.611 161.076,80.417 161.384,80.417 162.103,81.135 162.103,82.132 162.454,82.483 162.454,82.51 163.438,83.494 163.731,83.494 v1(166.075,85.838)
NetTP41_1: TP41.1 U1.J17 | length 4.7
  Top Layer 1 _Signal w0.254: TP41.1@271.399,64.862 272.605,66.069 272.605,68.456 272.633,68.483 ; 272.633,68.452 272.633,68.483 ; U1.J17@272.981,68.88 272.981,68.859 272.71,68.588 272.71,68.547 272.646,68.483 272.633,68.483
NetU44_44: U44.44 U46.1 | length 10.5
  Top Layer 1 _Signal w0.254: U44.44@58.789,110.359 63.319,110.359 64.705,108.972 U46.1@64.705,104.987
NetU44_45: U44.45 U46.2 | length 8.5
  Top Layer 1 _Signal w0.254: U44.45@58.789,110.859 63.571,110.859 64.705,111.993 U46.2@64.705,114.093
NLDO1: C168.1 TP2.1 U3.P27 U5.14 | length 115.3
  Top Layer 1 _Signal w0.254: v1(158.686,82.152) 158.696,82.152 159.019,81.828 U3.P27@159.029,81.828
  Top Layer 1 _Signal w0.508: TP2.1@104.949,69.703 105.765,70.52 v1(105.765,70.585)
  Bottom Layer_Signals w0.254: v1(158.686,82.152) 159.379,82.845 159.379,83.335 159.661,83.617 159.661,84.455 159.81,84.604 159.892,84.604
  Bottom Layer_Signals w0.508: v1(98.805,61.324) 98.78,61.349 v1(98.78,62.04) 98.751,62.07 v1(98.751,62.548) 98.751,63.625 105.738,70.612 106.359,71.233 106.359,75.543 140.631,109.815 145.478,109.815 145.609,109.683 148.343,109.683 148.624,109.964 157.435,109.964 160.918,106.482 160.918,89.1 160.496,88.678 160.496,88.476 159.25,87.23 159.25,85.63 159.829,85.051 159.829,85.038 159.909,84.958 159.909,84.621 159.892,84.604
NLDO2: C169.1 C303.2 C308.2 TP28.1 TP60.1 U3.L15 U3.N12 U5.12 | length 5.3
  Top Layer 1 _Signal w0.254: 110.747,69.723 110.786,69.723 111.005,69.505 TP60.1@111.706,69.505 ; v1@149.066,82.203 v1(149.057,82.212) 149.097,82.212 149.245,82.361 149.267,82.361 149.267,82.465 U3.N12@149.279,82.478 ; v1(150.903,83.434) 151.229,83.76 U3.L15@151.229,83.778
  Bottom Layer_Signals w0.254: C303.2@147.542,82.961 C303.2@147.552,82.961 ; C308.2@148.58,82.998 148.57,82.998 148.533,82.961 C303.2@147.552,82.961 ; v1(148.932,81.503) 148.932,81.542 148.544,81.93 148.544,82.141 148.148,82.537 147.765,82.537 147.565,82.738 147.565,82.948 C303.2@147.552,82.961 ; v1@148.98,82.175 149.018,82.212 v1(149.057,82.212)
  other v1: 109.175,69.733 109.985,69.723
NLDO3: C171.1 C463.1 C464.1 C470.1 TP29.1 U3.AA9 U3.AB9 U5.11 | length 21.3
  Top Layer 1 _Signal w0.305: C171.1@101.505,61.115 102.503,62.113 TP29.1@102.503,63.292 102.583,63.292 102.878,63.587 103.024,63.587 103.455,64.018 103.491,64.018 C463.1@103.589,64.115 ; U3.AA9@147.329,77.278 U3.AB9@147.329,76.628 147.333,76.628 147.658,76.303 v1(147.677,76.303) v1@147.744,76.303
  Top Layer 1 _Signal w0.508: 120.405,64.115 125.641,69.351 130.733,69.351 v1(130.745,69.339) 130.75,69.344 132.289,69.344 v1(132.305,69.36) 133.053,69.36 v1(133.064,69.371)
  Bottom Layer_Signals w0.305: C464.1@147.281,75.988 147.281,75.992 147.574,76.285 148.394,76.285 148.421,76.257 C470.1@148.431,76.257
  other v1: 129.394,69.344 131.541,69.344 129.938,69.355
NLDO4: C172.1 C459.2 C460.1 TP27.1 U3.AH14 U3.AJ14 U5.10 | length 5.4
  Top Layer 1 _Signal w0.254: v1(150.322,72.432) 150.322,72.453 150.579,72.71 U3.AH14@150.579,72.728 U3.AJ14@150.579,72.078
  Top Layer 1 _Signal w0.508: TP27.1@105.147,61.894 v1(105.147,62.634)
  L6_Signals w0.508: 149.615,73.616 149.615,73.012 150.082,72.545 150.209,72.545 v1(150.322,72.432)
  Bottom Layer_Signals w0.254: C460.1@149.612,72.228 149.622,72.228 149.797,72.404 150.281,72.404 150.316,72.438 150.35,72.404 150.35,72.321 150.35,71.856 150.445,71.761 150.445,71.291 150.45,71.287 C459.2@150.495,71.287
  other v1: 125.515,67.118 126.278,67.112 127.088,67.101 127.094,67.703 126.272,67.747 127.694,67.741
NLDO5: C17.2 C167.1 C454.1 C471.2 TP67.1 U3.AD3 U3.AE8 U3.AH10 U3.V20 U5.8 | length 39.6
  Top Layer 1 _Signal w0.254: U5.8@97.644,56.82 99.725,56.82 100.804,57.899 101.227,57.899 101.564,58.236 101.602,58.236 102.023,58.657 102.039,58.657 102.039,58.909 102.222,59.091 v1(102.222,59.13) 102.224,59.128 102.865,59.128 v1(102.868,59.125) 102.868,58.502 102.929,58.441 v1(102.929,58.402) 102.926,58.399 102.926,57.841 v1(102.923,57.838) 102.92,57.835 102.147,57.835 v1(102.144,57.833) ; v1@102.011,58.618 105.489,58.618 TP67.1@106.218,59.347 ; U3.AD3@143.429,75.328 143.429,75.318 143.73,75.017 v1(143.73,75.007) ; v1(146.368,74.367) U3.AE8@146.679,74.678 ; U3.AH10@147.979,72.728 147.979,72.746 148.221,72.988 148.221,73.005 v1(148.224,73.007) ; U3.V20@154.479,79.228 154.479,79.21 154.7,78.989 154.7,78.977 v1(154.74,78.937) v1@154.74,78.922
  L8_Signals w0.508: v1(143.73,75.007) 143.73,75.455 144.027,75.753 145.557,75.753 146.635,76.831 146.989,76.831 147.536,77.378 147.536,78.13 146.987,78.679 146.987,79.288 147.579,79.881 149.734,79.881 150.021,80.168 151.677,80.168 152.364,79.481 154.314,79.481 154.74,79.055 v1(154.74,78.937)
  Bottom Layer_Signals w0.254: v1(143.73,75.007) 143.749,75.007 144.811,73.945 145.946,73.945 v1(146.368,74.367) 146.368,74.327 146.517,74.178 146.517,73.751 146.538,73.73 146.538,73.564 v1@146.521,73.548 ; C17.2@146.473,71.489 146.477,71.493 146.802,71.493 146.943,71.634 C454.1@147.573,71.634 147.573,72.669 147.633,72.729 C471.2@147.633,72.739 147.633,72.749 147.864,72.98 148.196,72.98 v1(148.224,73.007) 147.633,73.598 v1(146.566,73.598)
  other v1: 101.206,57.899 101.585,58.236 102.011,58.629
nPHYRESET: U45.43
NPU_VSEL: U3.U32 U24.A1 | length 52.2
  Top Layer 1 _Signal w0.254: U3.U32@162.279,79.878 162.279,79.895 162.517,80.133 v1(162.517,80.15) ; v1(170.953,73.963) 170.674,73.684 170.674,58.925 185.247,44.352 U24.A1@185.247,39.357
  L3_Signals w0.254: v1(162.517,80.15) 162.545,80.122 162.545,79.96 163.178,79.327 163.433,79.327 163.674,79.087 164.198,79.087 165.032,78.252 165.525,78.252 166.892,76.885 168.073,76.885 169.489,75.469 169.489,75.428 v1(170.953,73.963)
nRESET1V8: D3.1 J1.4 J34.1 R14.2 U1.P19 | length 78.2
  Top Layer 1 _Signal w0.161: R14.2@260.419,72.909 260.899,72.909 261.086,72.722 v1(261.151,72.722) ; v1(262.53,90.687) 262.966,91.123 J1.4@262.966,92.462 ; v1(268.342,65.85) 268.343,65.851 268.643,65.851 269.14,66.349 269.14,67.101 268.981,67.26 U1.P19@268.981,67.28 ; D3.1@290.199,86.941 289.273,86.015 289.273,78.9 290.29,77.883 290.29,77.833 J34.1@291.166,76.956
  L3_Signals w0.161: v1(268.342,65.85) 279.152,65.85 290.259,76.956 J34.1@291.166,76.956
  Bottom Layer_Signals w0.161: v1(262.53,90.687) 260.889,90.687 260.713,90.51 260.713,90.252 260.499,90.038 260.24,90.038 258.639,88.437 258.639,75.26 259.412,74.487 259.412,74.46 v1(261.151,72.722) 262.426,72.722 263.6,71.547 263.6,69.579 263.22,69.199 263.22,67.838 263.314,67.743 264.172,67.743 264.385,67.531 265.088,67.531 265.301,67.317 265.851,67.317 266.403,66.765 266.403,66.306 267.03,65.679 267.732,65.679 267.9,65.847 268.339,65.847 v1(268.342,65.85)
nRSTD: J3.10 R11.1 R14.1 | length 5.2
  Top Layer 1 _Signal w0.161: J3.10@256.631,76.112 256.631,75.403 256.908,75.126 257.456,75.126 258.57,74.011 R11.1@259.471,74.011 R14.1@259.471,72.911
OV: R209.1 R211.2 U42.8 | length 5.9
  Top Layer 1 _Signal w0.457: R209.1@27.192,27.768 27.242,27.768 27.264,27.79 27.264,27.84 27.903,28.479 R211.2@27.903,31.601 27.833,31.671 27.833,33.268 U42.8@27.805,33.296
P28.A_N: J333.10 U45.3 | length 11.6
  Top Layer 1 _Signal w0.111: J333.10@275.536,23.08 274.69,23.925 274.69,24.658 276.631,26.598 276.631,33.054 276.674,33.098 U45.3@276.674,33.503
P28.A_P: J333.11 U45.2 | length 11.6
  Top Layer 1 _Signal w0.111: J333.11@273.506,23.08 274.351,23.925 274.351,24.798 276.291,26.739 276.291,32.981 276.174,33.098 U45.2@276.174,33.503
P28.B_N: J333.5 U45.6 | length 17.1
  Top Layer 1 _Signal w0.111: J333.5@274.531,20.54 274.782,20.289 275.401,20.289 276.013,19.677 276.909,19.677 277.411,20.179 277.411,22.561 277.848,22.998 277.848,31.704 278.076,31.932 278.076,32.999 278.174,33.098 U45.6@278.174,33.503
P28.B_P: J333.4 U45.5 | length 13.5
  Top Layer 1 _Signal w0.111: J333.4@276.561,20.54 276.561,20.653 277.187,21.279 277.187,22.817 277.508,23.139 277.508,31.844 277.737,32.073 277.737,33.035 277.674,33.098 U45.5@277.674,33.503
P28.C_N: J333.2 U45.8 | length 14.2
  Top Layer 1 _Signal w0.111: U45.8@279.174,33.503 279.174,32.274 278.382,31.482 278.382,22.778 J333.2@280.621,20.54
P28.C_P: J333.3 U45.7 | length 13.5
  Top Layer 1 _Signal w0.111: J333.3@278.591,20.54 278.591,22.09 278.043,22.638 278.043,31.623 278.674,32.255 U45.7@278.674,33.503
P28.D_N: J333.9 U45.11 | length 15
  Top Layer 1 _Signal w0.111: J333.9@279.616,23.08 280.466,22.229 281.998,22.229 282.496,22.728 282.496,26.565 280.668,28.394 280.668,33.091 280.674,33.098 U45.11@280.674,33.503
P28.D_P: J333.8 U45.10 | length 11.5
  Top Layer 1 _Signal w0.111: U45.10@280.174,33.503 280.174,33.098 280.328,32.944 280.328,28.253 282.157,26.425 282.157,23.718 281.646,23.207 J333.8@281.646,23.08
P28.LED1: J333.13 R391.1 R392.2 U45.18 | length 34.2
  Bottom Layer_Signals w0.381: J333.13@285.096,7.59 285.096,10.809 288.481,14.195 288.481,20.816 288.244,21.053 288.244,21.446 288.481,21.682 288.481,36.288 v1(285.692,39.076)
P28.LED2: J333.17 R389.1 R390.2 U45.16 | length 38
  L3_Signals w0.381: J333.17@270.056,5.05 285.46,20.454 285.46,35.243 284.479,36.224 v1(284.479,36.237)
PCIE_CLK_N: C4.1 U1.R19 | length 1.5
  Top Layer 1 _Signal w0.161: U1.R19@268.181,67.28 268.19,67.28 268.631,66.84 v1(268.64,66.84)
  Bottom Layer_Signals w0.161: v1(268.64,66.84) 268.662,66.84 269.265,66.237 C4.1@269.265,66.227
PCIE_CLK_P: C3.1 U1.R18 | length 1.4
  Top Layer 1 _Signal w0.161: U1.R18@268.181,68.08 268.216,68.08 268.461,67.835 v1(268.496,67.835)
  Bottom Layer_Signals w0.161: C3.1@267.715,67.447 267.715,67.457 268.055,67.797 268.458,67.797 v1(268.496,67.835)
PCIE_RX_N: U1.W17
PCIE_RX_P: U1.V17
PCIE_TX_C_N: C2.1
PCIE_TX_C_P: C1.1
PCIE_TX_N: C2.2 U1.U19 | length 9.1
  Top Layer 1 _Signal w0.161: v1(266.177,64.902) 266.581,65.307 U1.U19@266.581,67.28
  Bottom Layer_Signals w0.161: C2.2@264.139,67.254 264.137,67.253 264.137,66.926 263.144,65.933 263.144,64.536 263.46,64.22 265.494,64.22 v1(266.177,64.902)
PCIE_TX_P: C1.2 U1.U18 | length 3.3
  Top Layer 1 _Signal w0.161: v1(266.225,68.413) 266.237,68.413 266.569,68.08 U1.U18@266.581,68.08
  Bottom Layer_Signals w0.161: C1.2@263.643,69.036 263.643,69.026 264.256,68.413 v1(266.225,68.413)
PEN_2V5: R334.2 U38.3 | length 1.6
  Top Layer 1 _Signal w0.381: R334.2@45.827,94.338 45.837,94.348 47.385,94.348 U38.3@47.395,94.359
PHYAD2: R387.1 R388.2 U45.15
PLDO4: C177.2 C434.1 C456.1 C472.2 C473.1 R75.2 TP35.1 U3.AE4 U3.AE5 U3.AJ10 U5.63 U18.12 | length 123.5
  Top Layer 1 _Signal w0.254: U3.AJ10@147.979,72.078 U3.AJ10@147.982,72.078 ; U3.AJ10@147.984,72.078 U3.AJ10@147.982,72.078 ; v1(148.297,72.391) 148.295,72.391 U3.AJ10@147.982,72.078
  Top Layer 1 _Signal w0.305: TP35.1@95.454,47.878 95.51,47.935 95.51,48.298 95.565,48.352 v1(95.565,48.378) 95.583,48.396 v1@96.008,48.396 ; v1(95.941,47.268) v1(95.435,47.268) 95.998,47.831 95.998,48.387 v1@96.008,48.396 ; v1(96.017,48.405) v1@96.008,48.396 ; v1(143.798,74.377) 144.104,74.683 144.632,74.683 144.634,74.681 144.726,74.681 U3.AE5@144.729,74.678 144.729,74.682 145.02,74.973 v1(145.026,74.973)
  Top Layer 1 _Signal w0.508: C434.1@36.388,76.591 36.388,76.516 36.609,76.295 37.222,76.295 v1(37.517,76)
  L8_Signals w0.305: v1(145.026,74.973) 146.379,74.973 147.283,74.069 147.788,74.069 ; 148.102,72.571 148.283,72.391 v1(148.297,72.391)
  Bottom Layer_Signals w0.254: v1(143.798,74.377) 144.569,73.606 144.787,73.606 145.146,73.247 145.146,73.202 C456.1@145.15,73.197 ; v1(148.297,72.391) 148.325,72.363 148.325,72.212 148.67,71.868 C473.1@148.67,71.822
  Bottom Layer_Signals w0.305: C472.2@144.514,74.851 144.618,74.955 145.007,74.955 v1(145.026,74.973)
  Bottom Layer_Signals w0.508: v1(37.517,76) 37.517,67.134 38.976,65.675 38.976,40.574 49.437,30.113 83.725,30.113 83.767,30.071 87.731,30.071 95.565,37.904 v1(95.565,48.378)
